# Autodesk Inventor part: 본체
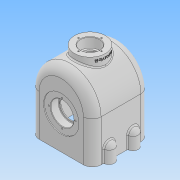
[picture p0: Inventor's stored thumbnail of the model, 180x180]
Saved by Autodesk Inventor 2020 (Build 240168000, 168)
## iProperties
Created: 2023-03
Part Number: 본체
Material: 일반
Document SubType Name: Modeling
Designer: user
Density: 1 g/cm^3
Appearance: 기본값
Author: user
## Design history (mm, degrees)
sketch "스케치1"
  geometry: L1 (-70, 94)-(70, 94); L2 (70, 94)-(70, 0); L3 (70, 0)-(-70, 0); L4 (-70, 0)-(-70, 94); L5 (-60, 94)-(-60, 0); L6 (60, 0)-(60, 94); A1 r 70 centre (0, 94) between (70, 94) and (-70, 94); A2 r 60 centre (0, 94) between (60, 94) and (-60, 94); 2 further points
  constraints: 12 end point, 4 point on circle, 3 parallel, 2 centre point, 2 midpoint, 2 point on line, 1 coincident, 1 horizontal, 1 perpendicular
  dimensions: "d1" = 94 distance of L3.end L1.start; "d2" = 140 distance of L2.end L3.end; "d3" = 10 radial gap between concentric circles of A1 A2; "d4" = 10 distance between parallel lines of L5 L4; "d5" = 10 distance between parallel lines of L2 L6
extrude "돌출1" new body sketch "스케치1" stored distance "d6" = 130; taper "d7" = 0 deg
sketch "스케치2"
  geometry: L1 (-60, 0)-(-60, 94) reference; L2 (60, 94)-(60, 0) reference; L3 (-70, 0)-(-70, 94) reference; L4 (70, 94)-(70, 0) reference; L5 (70, 0)-(60, 0) reference; L6 (60, 0)-(60, 94) reference; L7 (-60, 94)-(-60, 0) reference; L8 (-60, 0)-(-70, 0) reference; L9 (-60, 0)-(60, 0); A1 r 60 centre (0, 94) between (60, 94) and (-60, 94) reference; A2 r 70 centre (0, 94) between (70, 94) and (-70, 94) reference; A3 r 60 centre (0, 94) between (60, 94) and (-60, 94) reference; 1 further point
  constraints: 2 end point, 1 horizontal
extrude "돌출2" join sketch "스케치2" distance "d8" = 10; taper "d9" = 0 deg
sketch "스케치6"
  geometry: L1 (154, 55)-(0, 55) reference; L2 (0, 55)-(0, 65) reference; L3 (0, 65)-(164, 65) reference; L4 (164, 65)-(164, -65) reference; L5 (154, -55)-(154, 55) reference; L6 (164, -65)-(0, -65) reference; L7 (0, -65)-(0, -55) reference; L8 (0, -55)-(154, -55) reference; L9 (117, 65)-(117, 55); L10 (154, 55)-(94, 55) reference; L11 (117, 55)-(105.879, 43.879); L12 (103.757, 43)-(75, 43); L13 (75, 43)-(75, 65); L14 (75, 65)-(117, 65); A1 r 3 centre (103.757, 46) between (103.757, 43) and (105.879, 43.879); 3 further points
  constraints: 10 end point, 4 perpendicular, 4 point on line, 2 point on circle, 2 tangent, 1 centre point, 1 horizontal alignment
  dimensions: "d29" = 135 deg angle of L10 L11; "d30" = 22 distance of L12.end L13.end; "d50" = 75 distance of L2.end L13.end; "d51" = 60 diameter of point (105, 43) L13; "d52" = 3 radius of A1
revolve "회전3" sketch "스케치6" stored, may be unused: angle "d34" = 90 deg
sketch "스케치7"
  geometry: L1 (-70, 0)-(70, 0) reference; L2 (-70, 0)-(-70, 94) reference; L3 (70, 94)-(70, 0) reference; L4 (70, 0)-(-70, 0) reference; L5 (-70, 0)-(-70, 94) reference; L6 (70, 94)-(70, 0) reference; L7 (70, 0)-(-70, 0) reference; A1 r 70 centre (0, 94) between (70, 94) and (-70, 94) reference; A2 r 70 centre (0, 94) between (70, 94) and (-70, 94) reference; A3 r 70 centre (0, 94) between (70, 94) and (-70, 94) reference; 2 further points
  constraints: 1 vertical alignment
  dimensions: "d35" = 75 distance from line of L1 point (0, 75)
hole "구멍2" sketch "스케치7" at (0, 75) diameter "d36" = 52; stored, may be unused: countersink angle "d40" = 60 deg, drill point angle "d42" = 0 deg; dims "d37" = 6, "d38" = 80, "d39" = 2, "d41" = 18
sketch "스케치8"
  geometry: C1 r 26 at (0, 0) reference; 1 further point
hole "구멍3" sketch "스케치8" at (0, 0) diameter "d43" = 46; stored, may be unused: countersink angle "d47" = 60 deg, drill point angle "d49" = 0 deg; dims "d44" = 6, "d45" = 43, "d46" = 22, "d48" = 5
fillet "모깎기1" dims "d53" = 1
sketch "스케치9" dims "d54" = 60
  geometry: L1 (0, 0)-(0, 30); C1 r 26 at (0, 0) reference; 2 further points
  constraints: 2 coincident, 2 end point, 1 vertical, 1 vertical alignment, 2 other
hole "구멍4" sketch "스케치9" at (0, 30) diameter "d55" = 3.242; stored, may be unused: countersink angle "d59" = 60 deg, drill point angle "d61" = 118 deg; dims "d56" = 8, "d57" = 43, "d58" = 22, "d60" = 10
sketch "스케치12"
  geometry: L1 (140, 0)-(140, 130) reference; L2 (140, 104)-(140, 80); A1 r 12 centre (140, 92) between (140, 80) and (140, 104); 1 further point
  constraints: 3 point on line, 2 end point, 2 point on circle, 1 centre point
  dimensions: "d80" = 12 radius of A1; "d81" = 27 vertical distance of point (70, 65) A1.centre
extrude "돌출3" join sketch "스케치12" distance "d82" = 28; taper "d83" = 0 deg
node "작업 평면2"
sketch "스케치13"
  geometry: L1 (-70, 0)-(-70, 94) reference; L2 (70, 94)-(70, 28) reference; L3 (70, 28)-(82, 28) reference; L4 (82, 28)-(82, 0) reference; L5 (82, 0)-(60, 0) reference; L6 (60, 0)-(60, 94) reference; L7 (-60, 94)-(-60, 0) reference; L8 (-60, 0)-(-70, 0) reference; L9 (82, 28)-(70, 28) reference; L10 (70, 94)-(70, 0) reference; L11 (70, 40)-(70, 28); L12 (70, 28)-(82, 28); A1 r 60 centre (0, 94) between (60, 94) and (-60, 94) reference; A2 r 12 centre (70, 28) between (82, 28) and (70, 40); A3 r 70 centre (0, 94) between (70, 94) and (-70, 94) reference; 1 further point
  constraints: 4 end point, 2 point on circle, 1 centre point, 1 coincident, 1 collinear, 1 perpendicular, 1 point on line
revolve "회전4" sketch "스케치13" stored, may be unused: angle "d85" = 90 deg
sketch "스케치14"
  geometry: A1 r 12 centre (140, 92) between (140, 80) and (140, 104) reference; 1 further point
hole "구멍6" sketch "스케치14" at (140, 92) diameter "d86" = 10.106; stored, may be unused: countersink angle "d90" = 60 deg, drill point angle "d92" = 118 deg; dims "d87" = 24, "d88" = 43, "d89" = 22, "d91" = 26
fillet "모깎기2" dims "d93" = 20
fillet "모깎기3" dims "d94" = 3
node "작업 평면3"
sketch "스케치15"
  geometry: C1 r 35 at (0, 0); 1 further point
  constraints: 1 centre point, 1 coincident
  dimensions: "d96" = 70 diameter of C1
extrude "돌출4" join sketch "스케치15" stored distance "d97" = 28; taper "d98" = 0 deg
sketch "스케치16"
  geometry: C1 r 35 at (0, 0) reference
hole "구멍7" sketch "스케치16" at (0, 0) diameter "d99" = 34; stored, may be unused: countersink angle "d103" = 60 deg, drill point angle "d105" = 0 deg; dims "d100" = 24, "d101" = 43, "d102" = 22, "d104" = 26
sketch "스케치17" dims "d106" = 52
  geometry: L1 (0, 0)-(0, 26); C1 r 35 at (0, 0) reference; 1 further point
  constraints: 2 coincident, 2 end point, 1 vertical, 1 vertical alignment, 2 other
hole "구멍8" sketch "스케치17" at (0, 26) diameter "d107" = 3.242; stored, may be unused: countersink angle "d111" = 60 deg, drill point angle "d113" = 118 deg; dims "d108" = 8, "d109" = 43, "d110" = 22, "d112" = 10
fillet "모깎기4" dims "d117" = 3
chamfer "모따기1" distance "d118" = 1; stored, may be unused: second distance "d119" = 2, angle "d120" = 45 deg
fillet "모깎기5" dims "d121" = 10
node "작업 평면4"
sketch "스케치18"
  geometry: 1 further point
sketch "스케치19"
  geometry: L1 (1.739, 31.03)-(1.739, -31.03); L2 (1.739, -31.03)-(-17.739, -31.03); L3 (-17.739, -31.03)-(-17.739, 31.03); L4 (-17.739, 31.03)-(1.739, 31.03); L5 (-8, 31.03)-(-8, -31.03); L6 (-17.739, 0)-(1.739, 0); L7 (0, -35)-(0, 35) reference; 2 further points
  constraints: 5 midpoint, 4 end point, 1 horizontal alignment, 2 other
  dimensions: "d122" = 8 distance between parallel lines of L7 L5
feature "엠보싱2" sketch "스케치19" dims "d123" = 0.5, "d124" = 0
sketch "스케치20"
  geometry: L1 (-10, 20)-(-10, 110) reference; L2 (110, 20)-(110, 110) reference; L3 (100, 120)-(0, 120) reference; L4 (0, 120)-(0, 10); L5 (0, 10)-(100, 10) reference; L6 (100, 120)-(100, 10); A1 r 10 centre (0, 20) between (-10, 20) and (0, 10) reference; A2 r 10 centre (0, 110) between (0, 120) and (-10, 110) reference; A3 r 10 centre (100, 110) between (110, 110) and (100, 120) reference; A4 r 10 centre (100, 20) between (100, 10) and (110, 20) reference; 1 further point
  constraints: 4 end point, 1 perpendicular, 1 vertical
extrude "돌출5" cut sketch "스케치20" distance "d125" = 40; taper "d126" = 0 deg
node "솔리드1"
mirror "미러1"
pattern_circular "원형 패턴1" dims angle "d63" = 360 deg
mirror "미러3"
mirror "미러4"
mirror "미러5"
pattern_circular "원형 패턴3" dims angle "d115" = 360 deg
node "절단 모서리 투영1"
node "절단 모서리 투영4"
node "절단 모서리 투영5"
node "절단 모서리 투영6"
node "절단 모서리 투영7"
feature "A9D066F2-1C7D-4E18-AEED-F7BC21143FA4" dims "d36" = 52, "d37" = 6, "d38" = 80, "d39" = 2, "d40" = 60 deg, "d41" = 18, "d42" = 0
other parameters: "d84" = 27, "d95" = 178
